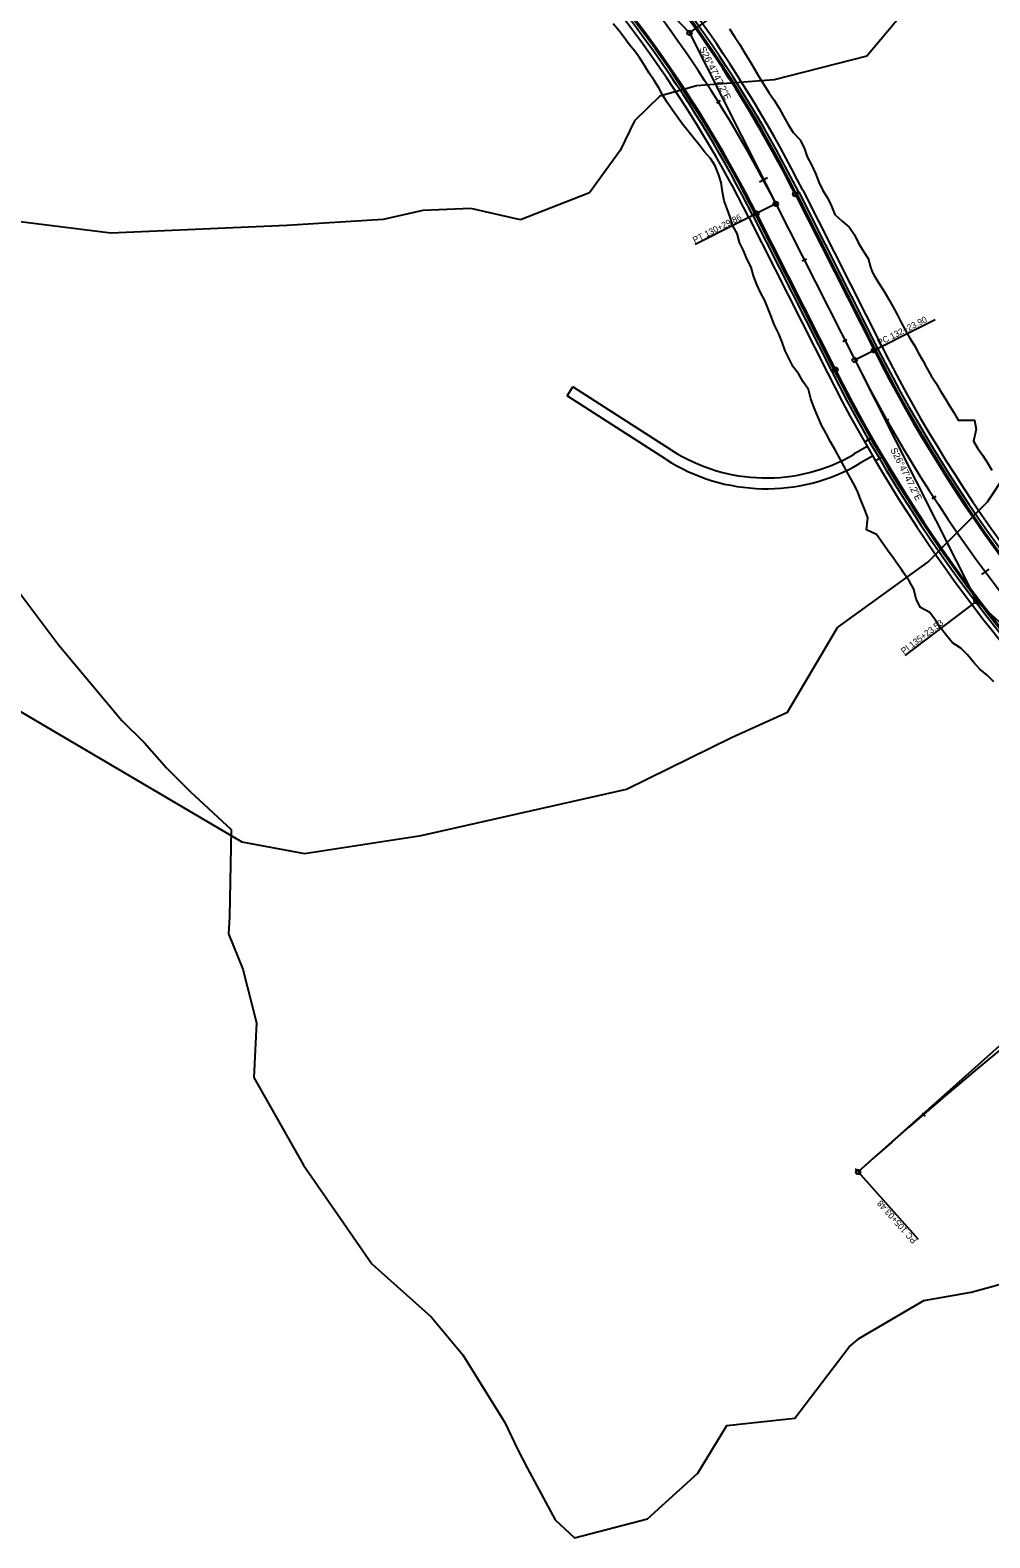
# Model space of a CAD drawing. Extents: x 1300404 to 1323571, y 234004 to 252077.
# Drawn here: x 1311368 to 1312432, y 237956 to 239629 of the extents above; entities that cross this region are included whole.
import ezdxf

# ---------------------------------------------------------------- set-up
doc = ezdxf.new("R2010")
doc.units = 0
for name, color, linetype in [('R_Const Limits', 7, 'Continuous'), ('R_Curb', 7, 'Continuous'), ('R_Flooplain', 7, 'Continuous'), ('R_Horz Alg Annot', 7, 'Continuous'), ('R_Horz Alg Annot Leader', 7, 'Continuous'), ('R_Horz Alg Major Ticks', 7, 'Continuous'), ('R_Horz Alg Minor Ticks', 7, 'Continuous'), ('R_Horz Alg Tangents', 7, 'Continuous'), ('R_Horz Alg Tangents Text', 7, 'Continuous'), ('R_Information', 7, 'Continuous'), ('R_Lane Edge', 7, 'Continuous'), ('R_Proposed', 7, 'Continuous'), ('R_Sidewalk Edge', 7, 'Continuous')]:
    doc.layers.add(name, color=color, linetype=linetype)

msp = doc.modelspace()

# ---------------------------------------------------------------- linework, layer by layer
at = {"layer": 'R_Const Limits'}
for points in [[(1312436.7, 238905.6), (1312429.4, 238913), (1312421.2, 238919.8), (1312414.3, 238927.6), (1312407.6, 238935.6), (1312400.1, 238943), (1312391, 238949.1), (1312384.3, 238957.2), (1312377.9, 238965.2), (1312377.8, 238965.4), (1312371.9, 238974.1), (1312365.7, 238982.5), (1312355.6, 238988.1), (1312350.5, 238997.3), (1312347.9, 239008.4), (1312342.9, 239017.6), (1312337.1, 239026.4), (1312334.4, 239030.5), (1312331.1, 239034.9), (1312325, 239043.4), (1312318.9, 239051.9), (1312312.8, 239060.4), (1312306.8, 239069), (1312295.7, 239074.3), (1312296.9, 239087.5), (1312293.4, 239097.6), (1312289.4, 239107.4), (1312285.5, 239117.2), (1312280.7, 239126.5), (1312275.6, 239135.6), (1312270.7, 239144.7), (1312265.8, 239154), (1312260.7, 239163), (1312255.7, 239172.1), (1312250.7, 239181.3), (1312245.8, 239190.4), (1312241.7, 239200), (1312237.6, 239209.6), (1312234, 239219.5), (1312231.4, 239229.8), (1312225.5, 239238.3), (1312220.7, 239247.1), (1312214.4, 239255.1), (1312209.8, 239263.9), (1312205.4, 239272.9), (1312202.2, 239282.5), (1312198.3, 239291.8), (1312193.9, 239300.7), (1312192, 239305.1), (1312190.4, 239310.2), (1312186.7, 239319.5), (1312182.7, 239328.7), (1312178.2, 239337.6), (1312173.8, 239346.6), (1312170.3, 239356), (1312167.5, 239365.8), (1312163, 239374.8), (1312159.1, 239384), (1312154.6, 239392.9), (1312152.1, 239402.9), (1312147.2, 239411.6), (1312144.4, 239421), (1312141.2, 239430.2), (1312137.9, 239439.3), (1312136, 239449.3), (1312134.4, 239459.5), (1312131.6, 239469), (1312127.6, 239477.9), (1312122.4, 239486.1), (1312116.1, 239493.7), (1312110.1, 239501.4), (1312103.9, 239509), (1312097.9, 239516.7), (1312091.6, 239524.2), (1312085.8, 239532), (1312080.3, 239539.9), (1312079.7, 239540.8), (1312074.9, 239548), (1312069.8, 239556.2), (1312065.2, 239564.7), (1312060, 239572.9), (1312054.7, 239581), (1312049.5, 239589.2), (1312049, 239590), (1312044.3, 239597.4), (1312038.5, 239605.1), (1312032.5, 239612.7), (1312026.7, 239620.5), (1312020.9, 239628.2), (1312014.7, 239635.6)], [(1312143.6, 239630.1), (1312149.3, 239621.5), (1312155, 239612.8), (1312160.4, 239603.9), (1312165.2, 239596), (1312165.8, 239595), (1312171.1, 239586.1), (1312176.2, 239577.1), (1312181.6, 239568.2), (1312187.2, 239559.5), (1312193.1, 239550.9), (1312198.8, 239542.2), (1312203.6, 239533), (1312208.6, 239523.9), (1312214.1, 239515.1), (1312221.6, 239507.4), (1312226.4, 239498.2), (1312229.6, 239488.1), (1312234.6, 239479), (1312239.1, 239469.6), (1312242.7, 239459.8), (1312247, 239450.8), (1312252.5, 239442.4), (1312256.7, 239433.3), (1312260.6, 239424), (1312268.5, 239416.8), (1312276.7, 239409.8), (1312282.2, 239401.4), (1312286.7, 239392.4), (1312291.9, 239383.9), (1312297.3, 239375.3), (1312299.9, 239365.5), (1312301.8, 239360.6), (1312304.1, 239356.4), (1312309.4, 239347.9), (1312314.7, 239339.3), (1312319.9, 239330.7), (1312324.8, 239322), (1312329.5, 239313.2), (1312334.1, 239304.4), (1312338.9, 239295.5), (1312343.6, 239287), (1312348.7, 239278.8), (1312353.3, 239270.4), (1312358, 239262.1), (1312362.4, 239253.5), (1312367.4, 239245.3), (1312372.5, 239237.2), (1312377.4, 239228.9), (1312382.3, 239220.7), (1312387.3, 239212.5), (1312392.3, 239204.3), (1312397.1, 239196), (1312415.4, 239195.9), (1312417.1, 239185.8), (1312414.1, 239172.7), (1312419.2, 239164.7), (1312424.4, 239156.6), (1312429.6, 239148.6), (1312434.6, 239140.4)], [(1311344.3, 239020.4), (1311400.1, 238946.5), (1311469.8, 238862.9), (1311495.1, 238838.2), (1311519.4, 238810.5), (1311546, 238783.8), (1311591, 238741.9), (1311589.3, 238645.4), (1311589.2, 238645.1), (1311588.2, 238626.3), (1311604, 238587.1), (1311619.1, 238527.4), (1311616.2, 238466.8), (1311671.3, 238369.5), (1311712.1, 238310.3), (1311747.1, 238260.1), (1311812.8, 238201.2), (1311848.1, 238159.1), (1311894.5, 238084.1), (1311908.9, 238053.8), (1311919.4, 238033.9), (1311950.3, 237976.2), (1311971.7, 237956.2), (1312052.6, 237977.2), (1312108.6, 238028), (1312140.7, 238080.8), (1312216, 238088.9), (1312276.5, 238168), (1312287.8, 238177.8), (1312359.3, 238219.4), (1312411.7, 238228.8), (1312514.5, 238257)]]:
    msp.add_lwpolyline(points, dxfattribs=at)
at = {"layer": 'R_Curb'}
for p, q in [((1312217.3, 239447.2), (1312304.8, 239274)), ((1312217.8, 239447.4), (1312305.2, 239274.2)), ((1312172.2, 239424.4), (1312259.7, 239251.2)), ((1312172.7, 239424.6), (1312260.2, 239251.4))]:
    msp.add_line(p, q, dxfattribs=at)
for centre, radius, start, end in [((1310916.4, 238790.1), 1457.4, 26.7964, 43.6667), ((1310916.4, 238790.1), 1457.9, 26.7964, 43.6667), ((1310916.4, 238790.1), 1406.9, 26.7964, 43.6667), ((1310916.4, 238790.1), 1407.4, 26.7964, 43.6667), ((1313743.7, 240000.7), 1612, 206.7964, 227.5411), ((1313743.7, 240000.7), 1611.5, 206.7964, 227.5411), ((1313743.7, 240000.7), 1662.5, 206.7964, 226.4144), ((1313743.7, 240000.7), 1662, 206.7964, 226.4144)]:
    msp.add_arc(centre, radius, start, end, dxfattribs=at)
at = {"layer": 'R_Flooplain'}
for p, q in [((1312350.1, 239664.6), (1312296, 239599.6)), ((1312296, 239599.6), (1312193.1, 239573.4)), ((1312106.9, 239566.8), (1312066.4, 239555.5)), ((1312193.1, 239573.4), (1312106.9, 239566.8)), ((1312066.4, 239555.5), (1312038.4, 239527.9)), ((1312038.4, 239527.9), (1312022.3, 239494.9)), ((1312022.3, 239494.9), (1311988.5, 239448.2)), ((1311988.5, 239448.2), (1311912, 239418.1)), ((1311803.6, 239428.4), (1311759.6, 239418.6)), ((1311856.9, 239430.6), (1311803.6, 239428.4)), ((1311912, 239418.1), (1311856.9, 239430.6)), ((1311457.6, 239403.5), (1311325.3, 239419.9)), ((1311652.8, 239411.8), (1311457.6, 239403.5)), ((1311759.6, 239418.6), (1311652.8, 239411.8)), ((1312429.9, 239105.3), (1312474.4, 239173.3)), ((1312363.7, 239038.5), (1312429.9, 239105.3)), ((1312263.3, 238966.1), (1312363.7, 239038.5)), ((1312207.8, 238872.1), (1312263.3, 238966.1)), ((1311346.8, 238879.2), (1311603, 238728.4)), ((1312145.9, 238843.8), (1312207.8, 238872.1)), ((1312029.3, 238786.8), (1312145.9, 238843.8)), ((1311801.7, 238735.3), (1312029.3, 238786.8)), ((1311603, 238728.4), (1311672.5, 238715.2)), ((1311672.5, 238715.2), (1311801.7, 238735.3))]:
    msp.add_line(p, q, dxfattribs=at)
at = {"layer": 'R_Horz Alg Annot Leader'}
for points in [[(1312099.2, 239625.5), (1312180.9, 239683.2)], [(1312195, 239435.9), (1312105.7, 239390.8)], [(1312282.5, 239262.7), (1312371.7, 239307.8)], [(1312417.6, 238995.2), (1312337.9, 238934.8)], [(1312286.4, 238362.1), (1312353, 238287.5)]]:
    msp.add_lwpolyline(points, dxfattribs=at)
at = {"layer": 'R_Horz Alg Major Ticks'}
for points in [[(1312185.7, 239464.7), (1312176.9, 239460.1)], [(1312431.1, 239030.8), (1312423.1, 239024.9)], [(1312283.1, 238365.8), (1312289.7, 238358.4)]]:
    msp.add_lwpolyline(points, dxfattribs=at)
at = {"layer": 'R_Horz Alg Minor Ticks'}
for points in [[(1312133.4, 239550.3), (1312129.2, 239547.7)], [(1312228.9, 239374.4), (1312224.4, 239372.2)], [(1312273.9, 239285.1), (1312269.5, 239282.9)], [(1312320.5, 239196.8), (1312316.2, 239194.3)], [(1312372.3, 239111.4), (1312368.1, 239108.7)], [(1312357.3, 238427.7), (1312360.5, 238423.9)]]:
    msp.add_lwpolyline(points, dxfattribs=at)
at = {"layer": 'R_Horz Alg Tangents'}
for p, q in [((1311952.6, 239779.2), (1312099.2, 239625.5)), ((1312099.2, 239625.5), (1312195, 239435.9)), ((1312282.5, 239262.7), (1312417.6, 238995.2)), ((1312417.6, 238995.2), (1312638.6, 238793)), ((1312286.4, 238362.1), (1312884.9, 238896.8))]:
    msp.add_line(p, q, dxfattribs=at)
at = {"layer": 'R_Information'}
for p, q in [((1311963.5, 239223), (1311970, 239233.1)), ((1312079.5, 239162.8), (1311970, 239233.1)), ((1312073, 239152.7), (1311963.5, 239223.1)), ((1312296.3, 239166.6), (1312281.7, 239158.1)), ((1312293.6, 239172), (1312301.5, 239176.6)), ((1312302.4, 239156.2), (1312287.8, 239147.8)), ((1312305.7, 239151.2), (1312313.6, 239155.8))]:
    msp.add_line(p, q, dxfattribs=at)
for radius in [194, 206]:
    msp.add_arc((1312184.4, 239325.9), radius, 237.2681, 300.1205, dxfattribs=at)
at = {"layer": 'R_Lane Edge'}
for p, q in [((1312216.4, 239446.7), (1312303.9, 239273.5)), ((1312173.6, 239425.1), (1312261.1, 239251.9)), ((1312293.6, 239172), (1312293.3, 239171.8)), ((1312305.7, 239151.2), (1312305.4, 239151.1))]:
    msp.add_line(p, q, dxfattribs=at)
for centre, radius, start, end in [((1310916.4, 238790.1), 1456.4, 26.7964, 43.6667), ((1310916.4, 238790.1), 1408.4, 26.7964, 43.6667), ((1313743.7, 240000.7), 1613, 206.7964, 227.5411), ((1313743.7, 240000.7), 1661, 206.7964, 226.4144)]:
    msp.add_arc(centre, radius, start, end, dxfattribs=at)
at = {"layer": 'R_Proposed'}
for p, q in [((1312216.4, 239446.7), (1312303.9, 239273.5)), ((1312195, 239435.9), (1312282.5, 239262.7)), ((1312195, 239435.9), (1312282.5, 239262.7)), ((1312173.6, 239425.1), (1312261.1, 239251.9))]:
    msp.add_line(p, q, dxfattribs=at)
for centre in [(1312099.2, 239625.5), (1312216.4, 239446.7), (1312195, 239435.9), (1312173.6, 239425.1), (1312282.5, 239262.7), (1312303.9, 239273.5), (1312261.1, 239251.9), (1312417.6, 238995.2), (1312286.4, 238362.1)]:
    msp.add_circle(centre, 2.5, dxfattribs=at)
for centre, radius, start, end in [((1310916.4, 238790.1), 1432.4, 26.7964, 43.6667), ((1310916.4, 238790.1), 1432.4, 26.7964, 43.6667), ((1310916.4, 238790.1), 1456.4, 26.7964, 43.6667), ((1310916.4, 238790.1), 1408.4, 26.7964, 43.6667), ((1313743.7, 240000.7), 1637, 206.7964, 227.5411), ((1313743.7, 240000.7), 1637, 206.7964, 227.5411), ((1313743.7, 240000.7), 1613, 206.7964, 227.5411), ((1313743.7, 240000.7), 1661, 206.7964, 226.4144), ((1316103.6, 234089.3), 5729.6, 115.83028, 131.77722)]:
    msp.add_arc(centre, radius, start, end, dxfattribs=at)
at = {"layer": 'R_Sidewalk Edge'}
for p, q in [((1312220.4, 239448.7), (1312307.9, 239275.5)), ((1312224.9, 239451), (1312312.4, 239277.8)), ((1312165.1, 239420.8), (1312252.6, 239247.6)), ((1312169.6, 239423), (1312257, 239249.8))]:
    msp.add_line(p, q, dxfattribs=at)
for centre, radius, start, end in [((1310916.4, 238790.1), 1460.9, 26.7964, 43.6667), ((1310916.4, 238790.1), 1465.9, 26.7964, 43.6667), ((1310916.4, 238790.1), 1398.9, 26.7964, 43.6667), ((1310916.4, 238790.1), 1403.9, 26.7964, 43.6667), ((1313743.7, 240000.7), 1603.5, 206.7964, 227.5411), ((1313743.7, 240000.7), 1608.5, 206.7964, 227.5411), ((1313743.7, 240000.7), 1670.5, 206.7964, 226.4144), ((1313743.7, 240000.7), 1665.5, 206.7964, 226.4144)]:
    msp.add_arc(centre, radius, start, end, dxfattribs=at)

# ---------------------------------------------------------------- texts
at = {"layer": 'R_Horz Alg Annot'}
for s, rotation, p in [('PT 130+29.86', 26.7964, (1312105.1, 239392.1)), ('PC 132+23.90', 26.7964, (1312309.8, 239278.2)), ('PI 135+23.53', 37.1688, (1312337, 238936)), ('PC 105+03.48', 131.7772, (1312351.9, 238286.5))]:
    msp.add_text(s, height=7, rotation=rotation, dxfattribs=at).set_placement(p)
at = {"layer": 'R_Horz Alg Tangents Text'}
for p in [(1312109.9, 239608), (1312321.8, 239163.2)]:
    msp.add_text('S26%%d47\'47.2"E', height=7.5, rotation=296.7964, dxfattribs=at).set_placement(p)

doc.saveas('drawing.dxf')
